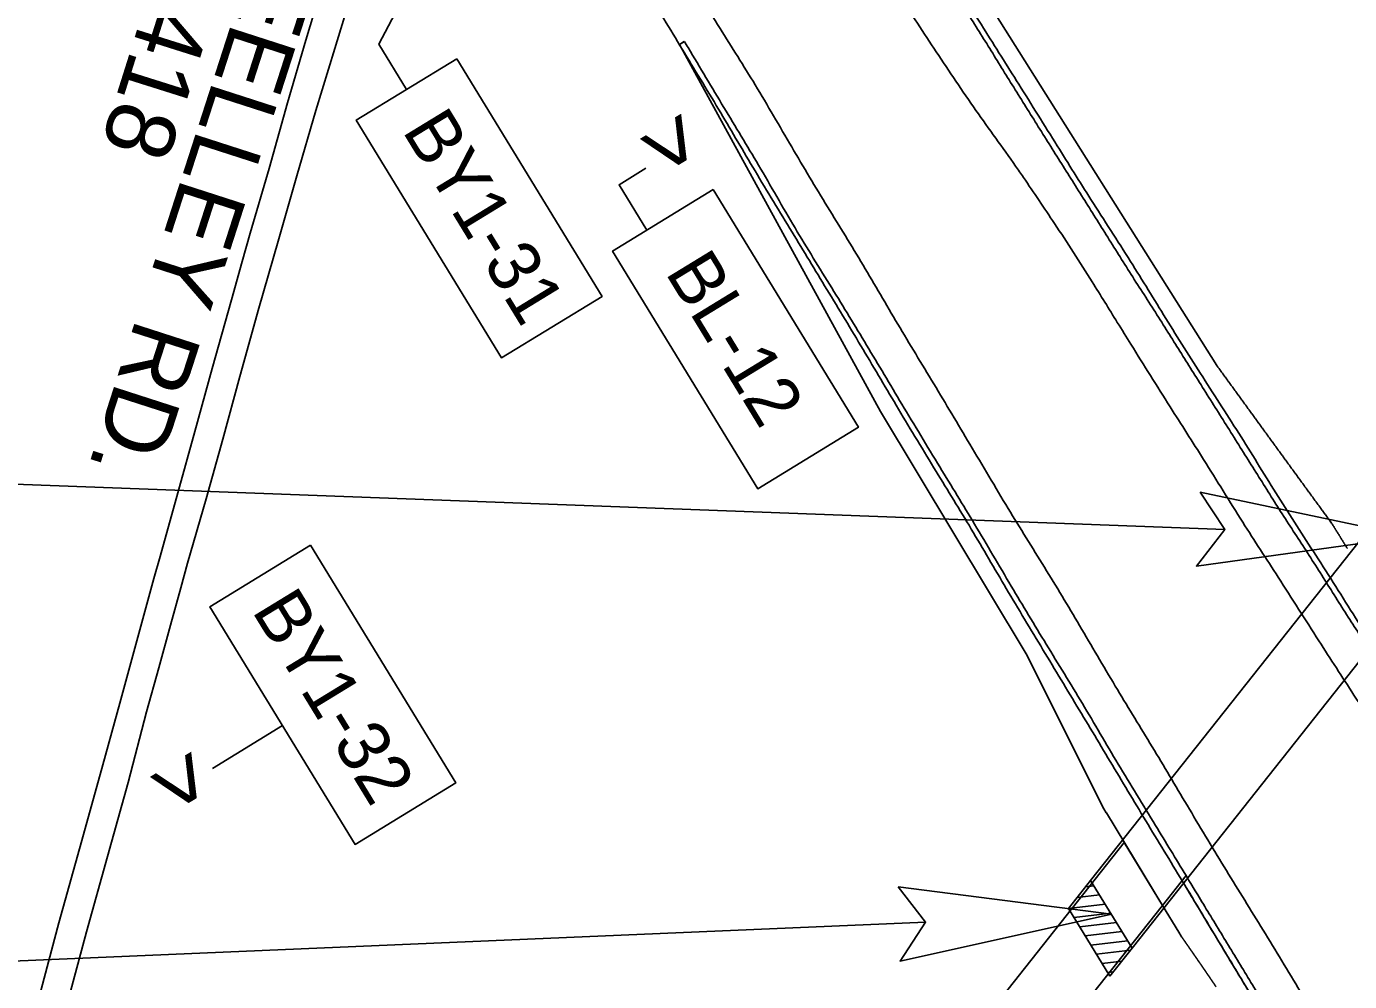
# Model space of a CAD drawing. Extents: x 1771071 to 1790027, y 804210 to 823391.
# Drawn here: x 1780972 to 1781920, y 813263 to 813948 of the extents above; entities that cross this region are included whole.
import ezdxf

# ---------------------------------------------------------------- set-up
doc = ezdxf.new("R2010")
doc.units = 0
for name, color, linetype in [('Default', 7, 'Continuous'), ('Exist Roads EOP', 7, 'Continuous'), ('Exist Structure Major Bridge Topo', 7, 'Continuous'), ('Old_Level_57', 7, 'Continuous'), ('Prop Conc Shoulder Berm Gutter', 7, 'Continuous'), ('Prop Superelevation Label', 7, 'Continuous'), ('Proposed Right of Way Monument PSD Text', 7, 'Continuous'), ('Scratch_Level_3', 7, 'Continuous'), ('Scratch_Level_4', 7, 'Continuous'), ('Scratch_Level_7', 7, 'Continuous'), ('Scratch_Level_8', 7, 'Continuous')]:
    doc.layers.add(name, color=color, linetype=linetype)

msp = doc.modelspace()

# ---------------------------------------------------------------- linework, layer by layer
at = {"layer": 'Default'}
for points in [[(1781284.45, 814049.54), (1781224.13, 813935.12), (1781244.03, 813902.55)], [(1781415.57, 813846.11), (1781396.44, 813834.22), (1781416.35, 813801.65)], [(1781155.08, 813446.43), (1781104.84, 813415.65)]]:
    msp.add_lwpolyline(points, dxfattribs=at)
for points in [[(1781280.09, 813924.58), (1781384.21, 813754.17), (1781312.09, 813710.11), (1781207.97, 813880.52)], [(1781463.88, 813830.7), (1781568, 813660.29), (1781495.88, 813616.22), (1781391.76, 813786.63)], [(1781175.14, 813575.7), (1781279.26, 813405.29), (1781207.14, 813361.22), (1781103.02, 813531.63)]]:
    msp.add_lwpolyline(points, close=True, dxfattribs=at)
at = {"layer": 'Exist Roads EOP'}
for points in [[(1780936.46, 813085.88), (1780950.82, 813141.45), (1780961.19, 813179.63), (1780966.06, 813197.9), (1780979.89, 813249.13), (1780994.64, 813304.94), (1781009.52, 813358.12), (1781024.45, 813411.35), (1781038.52, 813462.59), (1781062.76, 813551.91), (1781067.3, 813567.68), (1781080.07, 813613.28), (1781092.18, 813657.33), (1781104.79, 813702.49), (1781118.47, 813751.69), (1781126.23, 813779.12), (1781131.99, 813799.47), (1781145.53, 813845.86), (1781158.77, 813893.01), (1781171.72, 813937.82), (1781184.24, 813979.13)], [(1780956.18, 813081.02), (1780970.88, 813136.6), (1780985.61, 813191.49), (1780999.72, 813243.27), (1781014.58, 813298.52), (1781029.59, 813352.45), (1781044.54, 813405.69), (1781057.72, 813456.23), (1781066.36, 813487.82), (1781074.77, 813518.46), (1781082.17, 813545.28), (1781087.1, 813562.94), (1781100.27, 813608.87), (1781112.28, 813651.82), (1781124.56, 813696.7), (1781138.16, 813745.72), (1781151.94, 813793.7), (1781165.42, 813840.49), (1781179.04, 813887.42), (1781192.64, 813931.8), (1781204.91, 813972.13)]]:
    msp.add_lwpolyline(points, dxfattribs=at)
for points in [[(1781123.7, 814794.56), (1781151.95, 814749.7), (1781175.35, 814711.94), (1781204.02, 814667.22), (1781230.05, 814626.42), (1781255.51, 814585.11), (1781282.93, 814541.39), (1781309.04, 814500.81), (1781338.07, 814453.82), (1781362.44, 814415.66), (1781389.1, 814373.22), (1781417.2, 814328.4), (1781443.82, 814286), (1781469.22, 814245.27), (1781496.33, 814201.88), (1781523.28, 814159.28), (1781551.49, 814114.9), (1781575, 814076.8), (1781602.27, 814034.47), (1781628.68, 813992.42), (1781657.71, 813946.44), (1781682.97, 813906.24), (1781710.54, 813862.11), (1781734.73, 813823.58), (1781763.09, 813779.24), (1781788.41, 813738.38), (1781814.81, 813696.35), (1781842.37, 813653.36), (1781868.91, 813610.68), (1781895.83, 813568.71), (1781924.39, 813523.58), (1781950.61, 813481.8), (1781976.68, 813442.67), (1782004.37, 813401.37), (1782031.99, 813360.12), (1782060.77, 813317.53), (1782089.19, 813276.64), (1782119.2, 813233.31), (1782146.2, 813195.67), (1782175.13, 813155.14), (1782204.07, 813115.4), (1782233.24, 813075.72), (1782263.79, 813034.43), (1782294.03, 812994.29), (1782325.04, 812953.86), (1782354.41, 812916.21), (1782385, 812877.38), (1782417.21, 812837.26), (1782449.43, 812797.65), (1782479.54, 812761.76), (1782513.17, 812720.66), (1782543.05, 812684.98), (1782576.35, 812645.89), (1782608.48, 812608.74), (1782640.69, 812571.37), (1782677.39, 812530.96), (1782710.34, 812494.65), (1782741.2, 812460.83), (1782775.54, 812424.09), (1782810.15, 812387.02), (1782844.36, 812350.73), (1782880.69, 812313.19), (1782914.85, 812277.64), (1782949.87, 812242.16), (1782985.13, 812206.92), (1783022.44, 812170.42), (1783054.86, 812138.57), (1783094.75, 812100.54), (1783130.02, 812066.91), (1783162.74, 812036.24), (1783200.85, 812001.49), (1783239.6, 811965.96), (1783275.52, 811933.35), (1783312.46, 811900.79)], [(1781353.97, 814192.98), (1781399.9, 814221.73), (1781417.22, 814233.43), (1781422.64, 814236.53), (1781425.7, 814234.23), (1781432.12, 814224.33), (1781459.4, 814180.22), (1781487.02, 814136.24), (1781512.65, 814096.21), (1781539.63, 814053.84), (1781567.87, 814011.67), (1781596.67, 813970.33), (1781623.79, 813929.47), (1781652.24, 813887.5), (1781680.69, 813847.59), (1781686.32, 813839.47)], [(1782238.21, 812723.43), (1782209.62, 812761.64), (1782179.84, 812802.81), (1782150.96, 812844.35), (1782122.57, 812885.31), (1782093.83, 812926.21), (1782066.67, 812967.04), (1782037.68, 813009.45), (1782013.55, 813047.75), (1781985.99, 813090.96), (1781958.12, 813136.07), (1781932.71, 813176.73), (1781905.7, 813220.99), (1781881.5, 813261.19), (1781854.77, 813305.19), (1781828.51, 813347.84), (1781801.99, 813392.05), (1781777, 813433.82), (1781752.14, 813474.74), (1781726.57, 813518.08), (1781701.31, 813560.05), (1781675.36, 813602.16), (1781647.86, 813648.22), (1781622, 813691.51), (1781596.24, 813734.27), (1781571.35, 813776.65), (1781545.88, 813818.34), (1781520.17, 813861.28), (1781493.97, 813905.81), (1781468.78, 813946.29), (1781441.39, 813991.42), (1781416.22, 814033.89), (1781391.33, 814074.39), (1781364.79, 814119.62), (1781340.31, 814160.71), (1781334.13, 814172.47), (1781333.09, 814177.9), (1781337.32, 814182.2), (1781344.85, 814187.68)], [(1781347.63, 814087.49), (1781366.16, 814056.49), (1781391.11, 814015.51), (1781415.6, 813974.88), (1781441.68, 813931.39), (1781467.72, 813888.4), (1781492.24, 813846.9), (1781518.87, 813802.84), (1781543.79, 813761.81), (1781569.77, 813718.72), (1781595.1, 813676.09), (1781622.12, 813631.28), (1781647.29, 813589.99), (1781672.41, 813547.4), (1781698.68, 813503.48), (1781724.64, 813460.42), (1781750.09, 813418.03), (1781775.62, 813375.49), (1781802, 813331.98), (1781829.97, 813285.46), (1781854.79, 813244.49), (1781879.78, 813203.54), (1781906.05, 813160.78), (1781932.32, 813117.56), (1781958.63, 813075.56), (1781985.26, 813034.04), (1782012.68, 812991.46), (1782039.98, 812950.52), (1782069.08, 812907.49), (1782096.47, 812868.12), (1782126.2, 812826.48), (1782155.77, 812783.98), (1782185.85, 812741.94), (1782213.04, 812704.33)], [(1781686.32, 813839.47), (1781708.58, 813806.45), (1781735.55, 813764.59), (1781753.62, 813735.45)], [(1781753.62, 813735.45), (1781763.35, 813719.81), (1781791.45, 813674.99), (1781815.49, 813637.14), (1781843.53, 813592.22), (1781868.97, 813552.74), (1781898.1, 813507.17), (1781923.28, 813468.28), (1781952.83, 813422.87), (1781979.02, 813382.67), (1782005.43, 813343.16), (1782033.25, 813302.11), (1782044.92, 813285.25)]]:
    msp.add_spline(points, degree=3, dxfattribs=at)
at = {"layer": 'Exist Structure Major Bridge Topo'}
for p, q in [((1781949.02, 813606.37), (1781734.48, 813335.4)), ((1781978.74, 813557.73), (1781764.21, 813286.75)), ((1781734.48, 813335.4), (1781764.21, 813286.75)), ((1781730.9, 813330.87), (1781736.83, 813331.56)), ((1781718.61, 813315.34), (1781744.87, 813318.4)), ((1781724.76, 813323.11), (1781740.85, 813324.98)), ((1781718.61, 813315.34), (1781748.33, 813266.7)), ((1781722.63, 813308.76), (1781748.89, 813311.82)), ((1781726.65, 813302.18), (1781752.91, 813305.24)), ((1781730.67, 813295.61), (1781756.93, 813298.66)), ((1781734.69, 813289.03), (1781760.95, 813292.08)), ((1781738.71, 813282.45), (1781763.04, 813285.27)), ((1781742.73, 813275.87), (1781756.9, 813277.51)), ((1781746.75, 813269.29), (1781750.75, 813269.75))]:
    msp.add_line(p, q, dxfattribs=at)
at = {"layer": 'Prop Conc Shoulder Berm Gutter'}
for p, q in [((1781830.66, 813587.03), (1779981.09, 813656.14)), ((1781616.16, 813305.38), (1779771.36, 813226.61))]:
    msp.add_line(p, q, dxfattribs=at)
at = {"layer": 'Prop Superelevation Label'}
for points in [[(1781813.09, 813613.86), (1781963.88, 813582.05), (1781810.26, 813560.77), (1781830.66, 813587.03)], [(1781596.49, 813330.73), (1781749.35, 813311.07), (1781597.92, 813277.58), (1781616.16, 813305.38)]]:
    msp.add_lwpolyline(points, close=True, dxfattribs=at)
at = {"layer": 'Scratch_Level_3'}
for p, q in [((1781718.61, 813315.34), (1781734.48, 813335.4)), ((1781748.33, 813266.7), (1781764.21, 813286.75))]:
    msp.add_line(p, q, dxfattribs=at)
at = {"layer": 'Scratch_Level_4'}
msp.add_open_spline([(1781801.14, 813333.4), (1781801.43, 813332.92), (1781801.71, 813332.45), (1781802, 813331.98), (1781811.35, 813316.49), (1781820.62, 813300.95), (1781829.97, 813285.46), (1781838.22, 813271.79), (1781846.49, 813258.14), (1781854.79, 813244.49), (1781863.09, 813230.83), (1781871.43, 813217.18), (1781879.78, 813203.54), (1781888.51, 813189.27), (1781897.3, 813175.04), (1781906.05, 813160.78), (1781914.86, 813146.41), (1781923.51, 813131.93), (1781932.32, 813117.56), (1781940.96, 813103.48), (1781949.72, 813089.47), (1781958.63, 813075.56), (1781967.49, 813061.71), (1781976.38, 813047.88), (1781985.26, 813034.04), (1781994.39, 813019.84), (1782003.5, 813005.62), (1782012.68, 812991.46), (1782017.79, 812983.55), (1782023.02, 812975.72), (1782028.27, 812967.91)], degree=3, dxfattribs=at)
at = {"layer": 'Scratch_Level_8'}
for p, q in [((1781452.31, 814295.93), (1781824.99, 813704.52)), ((1781439.63, 813934.8), (1781443.18, 813936.95)), ((1781439.65, 813934.86), (1781443.2, 813937)), ((1781583.89, 813671.54), (1781439.65, 813934.86)), ((1781688.28, 813497.8), (1781583.89, 813671.54)), ((1781743.9, 813386.78), (1781688.28, 813497.8)), ((1781745.7, 813383.78), (1781743.9, 813386.78)), ((1781785.98, 813317.51), (1781745.74, 813383.72)), ((1781758.56, 813362.63), (1781524.14, 813066.53)), ((1781785.98, 813317.51), (1781758.56, 813362.63)), ((1781785.98, 813317.51), (1781758.56, 813362.63)), ((1781758.56, 813362.63), (1781785.98, 813317.51)), ((1781785.98, 813317.51), (1781758.56, 813362.63)), ((1781802.87, 813338.84), (1781785.98, 813317.51)), ((1781802.87, 813338.84), (1781785.98, 813317.51)), ((1781562.95, 813035.81), (1781785.98, 813317.51)), ((1781785.98, 813317.51), (1781797.68, 813298.27)), ((1781797.68, 813298.27), (1781799.47, 813295.29))]:
    msp.add_line(p, q, dxfattribs=at)
for points in [[(1782036.84, 813345.31), (1782034.55, 813348.71), (1782032.26, 813352.11), (1782029.98, 813355.51), (1782020.67, 813369.4), (1782011.41, 813383.31), (1782002.13, 813397.22), (1781993.04, 813410.86), (1781983.91, 813424.47), (1781974.91, 813438.16), (1781965.29, 813452.79), (1781955.81, 813467.52), (1781946.29, 813482.21), (1781937.61, 813495.59), (1781928.94, 813508.98), (1781920.31, 813522.38), (1781911.23, 813536.48), (1781902.42, 813550.76), (1781893.4, 813564.89), (1781884.42, 813578.95), (1781875.14, 813592.82), (1781866.25, 813606.94), (1781857.35, 813621.08), (1781848.47, 813635.22), (1781839.58, 813649.36), (1781830.55, 813663.74), (1781821.52, 813678.12), (1781812.49, 813692.5), (1781803.87, 813706.22), (1781795.25, 813719.95), (1781786.63, 813733.68), (1781777.48, 813748.24), (1781768.06, 813762.62), (1781758.91, 813777.18), (1781750.07, 813791.22), (1781741.29, 813805.3), (1781732.46, 813819.35), (1781723.6, 813833.46), (1781714.71, 813847.56), (1781705.85, 813861.67), (1781696.96, 813875.81), (1781688.12, 813889.97), (1781679.27, 813904.14), (1781670.62, 813918), (1781662.14, 813931.97), (1781653.44, 813945.8), (1781644.76, 813959.61), (1781636.07, 813973.41), (1781627.38, 813987.21), (1781618.36, 814001.53), (1781609.34, 814015.86), (1781600.32, 814030.18), (1781591.25, 814044.57), (1781581.98, 814058.84), (1781572.9, 814073.23), (1781564.02, 814087.29), (1781555.37, 814101.48), (1781546.51, 814115.56), (1781537.62, 814129.67), (1781528.61, 814143.71), (1781519.73, 814157.83), (1781510.84, 814171.94), (1781502.13, 814186.17), (1781493.22, 814200.27), (1781484.59, 814213.94), (1781475.76, 814227.48), (1781467.13, 814241.14), (1781457.86, 814255.82), (1781448.68, 814270.56), (1781439.4, 814285.23), (1781430.6, 814299.14), (1781421.76, 814313.01), (1781412.97, 814326.92), (1781404.09, 814340.98), (1781395.22, 814355.05), (1781386.37, 814369.12), (1781377.66, 814382.97), (1781369.09, 814396.9), (1781360.35, 814410.73), (1781351.27, 814425.1), (1781342.13, 814439.43), (1781333.03, 814453.79), (1781324.24, 814467.67), (1781315.42, 814481.52), (1781306.69, 814495.44), (1781297.8, 814509.59), (1781288.94, 814523.76), (1781280.06, 814537.92), (1781279.45, 814538.89), (1781278.85, 814539.86), (1781278.24, 814540.83)], [(1782006.35, 813009.47), (1782000.72, 813018.06), (1781995.11, 813026.67), (1781989.51, 813035.29), (1781980.46, 813049.25), (1781971.47, 813063.26), (1781962.68, 813077.39), (1781953.91, 813091.51), (1781945.15, 813105.63), (1781936.39, 813119.75), (1781927.8, 813133.61), (1781919.21, 813147.46), (1781910.64, 813161.33), (1781901.85, 813175.54), (1781893.18, 813189.8), (1781884.53, 813204.09), (1781875.65, 813218.76), (1781866.87, 813233.49), (1781857.97, 813248.14), (1781849.37, 813262.3), (1781840.77, 813276.46), (1781832.16, 813290.62), (1781823.74, 813304.48), (1781815.32, 813318.34), (1781806.9, 813332.2), (1781805.56, 813334.42), (1781804.21, 813336.63), (1781802.87, 813338.84)], [(1781799.47, 813295.29), (1781799.64, 813295.04), (1781799.82, 813294.79), (1781799.99, 813294.55), (1781800.16, 813294.3), (1781800.33, 813294.05), (1781800.5, 813293.81), (1781800.67, 813293.56), (1781800.85, 813293.31), (1781801.02, 813293.07), (1781801.19, 813292.82), (1781801.36, 813292.58), (1781801.53, 813292.33), (1781801.7, 813292.08), (1781801.88, 813291.84), (1781802.05, 813291.59), (1781802.22, 813291.34), (1781802.39, 813291.1), (1781802.56, 813290.85), (1781802.73, 813290.61), (1781802.9, 813290.36), (1781803.08, 813290.11), (1781803.25, 813289.87), (1781803.42, 813289.62), (1781803.59, 813289.37), (1781803.76, 813289.13), (1781803.93, 813288.88), (1781804.1, 813288.64), (1781804.27, 813288.39), (1781804.45, 813288.14), (1781804.62, 813287.9), (1781804.79, 813287.65), (1781804.96, 813287.41), (1781805.13, 813287.16), (1781805.3, 813286.91), (1781805.47, 813286.67), (1781805.64, 813286.42), (1781805.81, 813286.18), (1781805.98, 813285.93), (1781806.16, 813285.68), (1781806.33, 813285.44), (1781806.5, 813285.19), (1781806.67, 813284.95), (1781806.84, 813284.7), (1781807.01, 813284.46), (1781807.18, 813284.21), (1781807.35, 813283.96), (1781807.52, 813283.72), (1781807.69, 813283.47), (1781807.86, 813283.23), (1781808.03, 813282.98), (1781808.2, 813282.74), (1781808.37, 813282.49), (1781808.54, 813282.24), (1781808.71, 813282), (1781808.88, 813281.75), (1781809.05, 813281.51), (1781809.22, 813281.26), (1781809.39, 813281.02), (1781809.56, 813280.77), (1781809.73, 813280.52), (1781809.9, 813280.28), (1781810.07, 813280.03), (1781810.24, 813279.79), (1781810.41, 813279.54), (1781810.58, 813279.3), (1781810.75, 813279.05), (1781810.92, 813278.81), (1781811.09, 813278.56), (1781811.26, 813278.31), (1781811.43, 813278.07), (1781811.6, 813277.82), (1781811.77, 813277.58), (1781811.86, 813277.46), (1781811.94, 813277.33), (1781812.03, 813277.21)], [(1781812.03, 813277.21), (1781812.11, 813277.09), (1781812.2, 813276.96), (1781812.28, 813276.84), (1781812.45, 813276.6), (1781812.62, 813276.35), (1781812.79, 813276.1), (1781812.96, 813275.86), (1781813.13, 813275.61), (1781813.3, 813275.37), (1781813.47, 813275.12), (1781813.63, 813274.88), (1781813.8, 813274.63), (1781813.97, 813274.39), (1781814.14, 813274.14), (1781814.31, 813273.9), (1781814.48, 813273.65), (1781814.65, 813273.41), (1781814.82, 813273.16), (1781814.99, 813272.91), (1781815.16, 813272.67), (1781815.32, 813272.42), (1781815.49, 813272.18), (1781815.66, 813271.93), (1781815.83, 813271.69), (1781816, 813271.44), (1781816.17, 813271.2), (1781816.33, 813270.95), (1781816.5, 813270.71), (1781816.67, 813270.46), (1781816.84, 813270.21), (1781817.01, 813269.97), (1781817.18, 813269.72), (1781817.34, 813269.48), (1781817.51, 813269.23), (1781817.68, 813268.99), (1781817.85, 813268.74), (1781818.02, 813268.5), (1781818.18, 813268.25), (1781818.35, 813268.01), (1781818.52, 813267.76), (1781818.69, 813267.51), (1781818.85, 813267.27), (1781819.02, 813267.02), (1781819.19, 813266.78), (1781819.36, 813266.53), (1781819.52, 813266.29), (1781819.69, 813266.04), (1781819.86, 813265.8), (1781820.03, 813265.55), (1781820.19, 813265.31), (1781820.36, 813265.06), (1781820.53, 813264.81), (1781820.69, 813264.57), (1781820.86, 813264.32), (1781821.03, 813264.08), (1781821.2, 813263.83), (1781821.36, 813263.59), (1781821.53, 813263.34), (1781821.7, 813263.1), (1781821.86, 813262.85), (1781822.03, 813262.6), (1781822.2, 813262.36), (1781822.36, 813262.11), (1781822.53, 813261.87), (1781822.69, 813261.62), (1781822.86, 813261.38), (1781823.03, 813261.13), (1781823.19, 813260.89), (1781823.36, 813260.64), (1781823.52, 813260.39), (1781823.69, 813260.15), (1781823.86, 813259.9), (1781824.02, 813259.66), (1781824.19, 813259.41), (1781824.35, 813259.17), (1781824.38, 813259.12), (1781824.41, 813259.08), (1781824.44, 813259.04)]]:
    msp.add_open_spline(points, degree=3, dxfattribs=at)
for points in [[(1781443.2, 813937), (1781445.9, 813932.52), (1781471.54, 813889.64), (1781496.4, 813848.26), (1781522.58, 813803.24), (1781548.91, 813760.18), (1781573.83, 813719.25), (1781599.15, 813676.91), (1781626.34, 813631.86), (1781651.26, 813590.83), (1781677.56, 813546.42), (1781702.64, 813504.72), (1781728.58, 813462.19), (1781754.21, 813418.84), (1781780.98, 813374.83), (1781802.87, 813338.84)], [(1781824.99, 813704.52), (1781825.49, 813703.83), (1781826.02, 813703.1), (1781826.55, 813702.37), (1781827.08, 813701.64), (1781827.61, 813700.91), (1781828.14, 813700.18), (1781828.68, 813699.45)], [(1781828.68, 813699.45), (1781829.21, 813698.72), (1781829.74, 813697.98), (1781830.27, 813697.25), (1781830.8, 813696.52), (1781831.33, 813695.79), (1781831.86, 813695.06), (1781832.39, 813694.33), (1781832.92, 813693.6), (1781833.45, 813692.87), (1781833.98, 813692.14), (1781834.51, 813691.41), (1781835.04, 813690.68), (1781835.58, 813689.95), (1781836.11, 813689.22), (1781836.64, 813688.49), (1781837.17, 813687.76), (1781837.7, 813687.03), (1781838.23, 813686.3), (1781838.76, 813685.57), (1781839.29, 813684.84), (1781839.82, 813684.11), (1781840.35, 813683.38), (1781840.88, 813682.65), (1781841.41, 813681.92), (1781841.94, 813681.19), (1781842.47, 813680.46), (1781843.01, 813679.73), (1781843.54, 813679), (1781844.07, 813678.26), (1781844.6, 813677.53), (1781845.13, 813676.8), (1781845.66, 813676.07), (1781846.19, 813675.34), (1781846.72, 813674.61), (1781847.25, 813673.88), (1781847.78, 813673.15), (1781848.31, 813672.42), (1781848.84, 813671.69), (1781849.37, 813670.96), (1781849.9, 813670.23), (1781850.44, 813669.5), (1781850.97, 813668.77), (1781851.5, 813668.04), (1781852.03, 813667.31), (1781852.56, 813666.58), (1781853.09, 813665.85), (1781853.62, 813665.12), (1781854.15, 813664.39), (1781854.68, 813663.66), (1781855.21, 813662.93), (1781855.74, 813662.2), (1781856.27, 813661.47), (1781856.8, 813660.74), (1781857.33, 813660.01), (1781857.87, 813659.28), (1781858.4, 813658.55), (1781858.93, 813657.82), (1781859.46, 813657.09), (1781859.99, 813656.36), (1781860.52, 813655.63), (1781861.05, 813654.9), (1781861.58, 813654.17), (1781862.11, 813653.44), (1781862.64, 813652.71), (1781863.17, 813651.98), (1781863.7, 813651.26), (1781864.23, 813650.53), (1781864.77, 813649.8), (1781865.3, 813649.07), (1781865.83, 813648.34), (1781866.36, 813647.61), (1781866.89, 813646.88), (1781867.42, 813646.15), (1781867.95, 813645.42)], [(1781867.95, 813645.42), (1781868.48, 813644.69), (1781869.01, 813643.96), (1781869.54, 813643.23), (1781870.07, 813642.5), (1781870.6, 813641.77), (1781871.14, 813641.04), (1781871.67, 813640.31), (1781872.2, 813639.58), (1781872.73, 813638.85), (1781873.26, 813638.12), (1781873.79, 813637.4), (1781874.32, 813636.67), (1781874.85, 813635.94), (1781875.38, 813635.21), (1781875.91, 813634.48), (1781876.44, 813633.75), (1781876.98, 813633.02), (1781877.51, 813632.29), (1781878.04, 813631.56), (1781878.57, 813630.83), (1781879.1, 813630.1), (1781879.63, 813629.37), (1781880.16, 813628.65), (1781880.69, 813627.92), (1781881.22, 813627.19), (1781881.76, 813626.46), (1781882.29, 813625.73), (1781882.82, 813625), (1781883.35, 813624.27), (1781883.88, 813623.54), (1781884.41, 813622.82), (1781884.94, 813622.09), (1781885.47, 813621.36), (1781886, 813620.63), (1781886.54, 813619.9), (1781887.07, 813619.17), (1781887.6, 813618.44), (1781888.13, 813617.71), (1781888.66, 813616.99), (1781889.19, 813616.26), (1781889.72, 813615.53), (1781890.26, 813614.8), (1781890.79, 813614.07), (1781891.32, 813613.34), (1781891.85, 813612.62), (1781892.38, 813611.89), (1781892.91, 813611.16), (1781893.44, 813610.43), (1781893.98, 813609.7), (1781894.51, 813608.97), (1781895.04, 813608.25), (1781895.57, 813607.52), (1781896.1, 813606.79), (1781896.63, 813606.06), (1781897.16, 813605.33), (1781897.7, 813604.61), (1781898.23, 813603.88), (1781898.76, 813603.15), (1781899.29, 813602.42), (1781899.82, 813601.7), (1781900.35, 813600.97), (1781900.89, 813600.24), (1781901.42, 813599.51), (1781901.95, 813598.78), (1781902.48, 813598.06), (1781903.01, 813597.33), (1781903.55, 813596.6), (1781904.08, 813595.87), (1781904.61, 813595.15), (1781905.14, 813594.42), (1781905.67, 813593.69), (1781906.21, 813592.96), (1781907.27, 813591.51)], [(1781907.27, 813591.51), (1781907.56, 813591.05), (1781907.91, 813590.47), (1781908.27, 813589.9), (1781908.63, 813589.33), (1781908.98, 813588.76), (1781909.34, 813588.18), (1781909.69, 813587.61), (1781910.05, 813587.04), (1781910.41, 813586.47), (1781910.76, 813585.89), (1781911.12, 813585.32), (1781911.48, 813584.75), (1781911.83, 813584.18), (1781912.19, 813583.6), (1781912.55, 813583.03), (1781912.9, 813582.46), (1781913.26, 813581.89), (1781913.61, 813581.31), (1781913.97, 813580.74), (1781914.33, 813580.17), (1781914.68, 813579.6), (1781915.04, 813579.03), (1781915.4, 813578.45), (1781915.75, 813577.88), (1781916.11, 813577.31), (1781916.47, 813576.74), (1781916.82, 813576.16), (1781917.18, 813575.59), (1781917.54, 813575.02), (1781917.89, 813574.45), (1781918.25, 813573.88), (1781918.61, 813573.3)]]:
    msp.add_spline(points, degree=3, dxfattribs=at)

# ---------------------------------------------------------------- texts
at = {"layer": 'Old_Level_57'}
for p in [(1781405.33, 813867.06), (1781054.07, 813409.57)]:
    msp.add_text('>', height=46.95, rotation=301.43915, dxfattribs=at).set_placement(p)
at = {"layer": 'Proposed Right of Way Monument PSD Text'}
for s, p in [('BY1-31', (1781240.5, 813873.05)), ('BL-12', (1781429.02, 813771.42)), ('BY1-32', (1781132.66, 813528.89))]:
    msp.add_text(s, height=37.325, rotation=301.42495, dxfattribs=at).set_placement(p)
at = {"layer": 'Scratch_Level_7'}
for s, height, rotation, p in [('SR 3418', 49.208, 252.49304, (1781101.68, 814106.64)), ('NEELLEY RD.', 49.2075, 252.11197, (1781147.13, 814038.91))]:
    msp.add_text(s, height=height, rotation=rotation, dxfattribs=at).set_placement(p)

doc.saveas('drawing.dxf')
